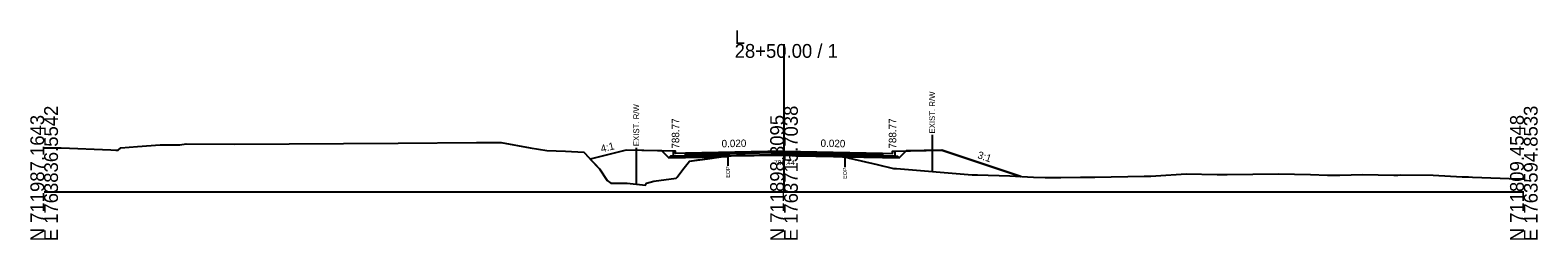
# Model space of a CAD drawing. Extents: x -26 to 5303, y -10 to 9578.
# Drawn here: x 997.2 to 1302.8, y 8490.3 to 8532.8 of the extents above; entities that cross this region are included whole.
import ezdxf

# ---------------------------------------------------------------- set-up
doc = ezdxf.new("R2010")
doc.units = 0
for name, color, linetype in [('Default', 7, 'Continuous'), ('Exist CMT Pavement', 7, 'Continuous'), ('Exist Cross Section Cell', 7, 'Continuous'), ('Exist XS Ground Line', 7, 'Continuous'), ('Old_Level_10', 7, 'Continuous'), ('Old_Level_3', 7, 'Continuous'), ('Prop CMT Conc Surface', 7, 'Continuous'), ('Prop CMT Concrete Structures', 7, 'Continuous'), ('Prop CMT Pvmt Course 1', 7, 'Continuous'), ('Prop CMT Pvmt Course 1 CG', 7, 'Continuous'), ('Prop CMT Pvmt Course 2', 7, 'Continuous'), ('Prop CMT Pvmt Course 3', 7, 'Continuous'), ('Prop CMT Pvmt Surface', 7, 'Continuous'), ('Prop CMT Slope Grass', 7, 'Continuous'), ('Prop CMT Subgrade Earthwork', 7, 'Continuous'), ('Prop XS Earthwork Shape', 7, 'Continuous'), ('Prop XS Hydro Elevations', 7, 'Continuous'), ('Prop XS SE Text', 7, 'Continuous'), ('Prop XS Side Slope Text', 7, 'Continuous'), ('Prop XS Wedging', 7, 'Continuous')]:
    doc.layers.add(name, color=color, linetype=linetype)

msp = doc.modelspace()

# ---------------------------------------------------------------- linework, layer by layer
at = {"layer": 'Exist CMT Pavement'}
msp.add_lwpolyline([(1138.63, 8507.34), (1140.35, 8507.37), (1140.82, 8507.37), (1142.14, 8507.38), (1143.12, 8507.39), (1143.93, 8507.41), (1145.04, 8507.42), (1146.22, 8507.43), (1147.51, 8507.42), (1149.4, 8507.43), (1150, 8507.44), (1150.75, 8507.45), (1151.57, 8507.39), (1152.42, 8507.35), (1152.87, 8507.34), (1153.48, 8507.33), (1154.66, 8507.31), (1155.53, 8507.3), (1156.45, 8507.28), (1157.7, 8507.24), (1158.24, 8507.22), (1158.63, 8507.22), (1160.02, 8507.19), (1161.86, 8507.13), (1162.35, 8507.1)], dxfattribs=at)
at = {"layer": 'Exist Cross Section Cell'}
for p, q in [((1150, 8500), (1150, 8529.97)), ((1000, 8500), (1150, 8500)), ((1150, 8500), (1300, 8500))]:
    msp.add_line(p, q, dxfattribs=at)
at = {"layer": 'Exist XS Ground Line'}
msp.add_lwpolyline([(1000, 8508.95), (1001.98, 8508.94), (1003.47, 8508.91), (1013.52, 8508.53), (1014.52, 8508.48), (1015.02, 8508.46), (1015.52, 8508.96), (1018.9, 8509.23), (1023.51, 8509.57), (1025.85, 8509.57), (1027.51, 8509.57), (1028.77, 8509.76), (1038.57, 8509.66), (1071.74, 8509.91), (1087.66, 8509.99), (1089.89, 8509.99), (1092.67, 8509.99), (1098.55, 8508.92), (1101.94, 8508.37), (1105.73, 8508.28), (1109.41, 8508.03), (1112.56, 8504.71), (1114.12, 8502.29), (1114.87, 8501.77), (1118.19, 8501.76), (1121.89, 8501.36), (1122.14, 8501.79), (1123.59, 8502.22), (1128.15, 8502.82), (1128.35, 8503.02), (1129.5, 8504.52), (1130.86, 8506.27), (1135.94, 8507.04), (1138.63, 8507.33), (1139.28, 8507.35), (1140.35, 8507.37), (1140.82, 8507.37), (1142.14, 8507.38), (1143.12, 8507.39), (1143.93, 8507.41), (1145.04, 8507.42), (1145.72, 8507.43), (1146.22, 8507.43), (1147.51, 8507.42), (1149.4, 8507.43), (1150, 8507.44), (1150.75, 8507.45), (1151.57, 8507.39), (1152.42, 8507.35), (1152.87, 8507.34), (1153.48, 8507.33), (1154.66, 8507.31), (1155.53, 8507.3), (1157.7, 8507.24), (1158.24, 8507.22), (1158.63, 8507.22), (1160.02, 8507.19), (1161.86, 8507.13), (1162.35, 8507.1), (1163.27, 8506.87), (1168.86, 8505.56), (1172.19, 8504.75), (1172.78, 8504.73), (1188.18, 8503.47), (1188.62, 8503.46), (1189.22, 8503.44), (1195.78, 8503.25), (1200.59, 8502.99), (1202.93, 8502.91), (1206.11, 8502.91), (1210.08, 8502.98), (1213.01, 8503.01), (1222.99, 8503.17), (1224.39, 8503.2), (1225.42, 8503.27), (1231.55, 8503.68), (1237.84, 8503.52), (1238.7, 8503.54), (1239.87, 8503.52), (1250.25, 8503.69), (1256.76, 8503.57), (1260.16, 8503.43), (1262.66, 8503.43), (1267.31, 8503.52), (1273.64, 8503.43), (1274.47, 8503.43), (1275.08, 8503.44), (1281.62, 8503.41), (1287.49, 8503.08), (1288.78, 8503.06), (1289.58, 8503.01), (1298.89, 8502.67), (1300, 8502.65)], dxfattribs=at)
at = {"layer": 'Old_Level_10'}
for p, q in [((1180.04, 8511.54), (1180.04, 8504.14)), ((1120.04, 8508.96), (1120.04, 8501.56)), ((1138.63, 8507.33), (1138.63, 8505.28)), ((1162.35, 8507.1), (1162.35, 8505.05))]:
    msp.add_line(p, q, dxfattribs=at)
at = {"layer": 'Prop CMT Conc Surface'}
for points in [[(1128, 8507.77), (1128, 8508.27), (1127.5, 8508.27)], [(1130, 8507.89), (1128, 8507.77)], [(1170, 8507.89), (1172, 8507.77)], [(1172, 8507.77), (1172, 8508.27), (1172.5, 8508.27)]]:
    msp.add_lwpolyline(points, dxfattribs=at)
at = {"layer": 'Prop CMT Concrete Structures'}
for points in [[(1130, 8507.89), (1128, 8507.77), (1128, 8508.27), (1127.5, 8508.27)], [(1127.5, 8508.27), (1127.5, 8507.26), (1130, 8507.31)], [(1130, 8507.31), (1130, 8507.89)], [(1170, 8507.89), (1172, 8507.77), (1172, 8508.27), (1172.5, 8508.27)], [(1172.5, 8508.27), (1172.5, 8507.26), (1170, 8507.31)], [(1170, 8507.31), (1170, 8507.89)]]:
    msp.add_lwpolyline(points, dxfattribs=at)
at = {"layer": 'Prop CMT Pvmt Course 1'}
for points in [[(1150, 8508.29), (1130, 8507.89)], [(1130, 8507.89), (1130, 8507.64)], [(1130, 8507.64), (1138.63, 8507.81)], [(1138.63, 8507.81), (1150, 8508.04)], [(1138.63, 8507.81), (1138.63, 8507.81)], [(1150, 8508.04), (1150, 8508.29)], [(1150, 8508.29), (1170, 8507.89)], [(1150, 8508.04), (1150, 8508.04), (1150, 8508.04)], [(1162.35, 8507.79), (1150, 8508.04)], [(1170, 8507.64), (1162.35, 8507.79)], [(1162.35, 8507.79), (1162.35, 8507.79)], [(1170, 8507.89), (1170, 8507.64)]]:
    msp.add_lwpolyline(points, dxfattribs=at)
at = {"layer": 'Prop CMT Pvmt Course 1 CG'}
for points in [[(1130, 8507.31), (1127, 8507.25), (1126.66, 8506.91)], [(1130, 8506.97), (1130, 8507.31)], [(1170, 8507.31), (1173, 8507.25), (1173.34, 8506.91)], [(1170, 8506.97), (1170, 8507.31)], [(1126.66, 8506.91), (1130, 8506.97)], [(1173.34, 8506.91), (1170, 8506.97)]]:
    msp.add_lwpolyline(points, dxfattribs=at)
at = {"layer": 'Prop CMT Pvmt Course 2'}
for points in [[(1138.63, 8507.81), (1130, 8507.64)], [(1130, 8507.64), (1130, 8507.31)], [(1130, 8507.31), (1138.63, 8507.48)], [(1138.63, 8507.48), (1138.63, 8507.81)], [(1162.35, 8507.46), (1162.35, 8507.79)], [(1162.35, 8507.79), (1170, 8507.64)], [(1170, 8507.31), (1162.35, 8507.46)], [(1170, 8507.64), (1170, 8507.31)]]:
    msp.add_lwpolyline(points, dxfattribs=at)
at = {"layer": 'Prop CMT Pvmt Course 3'}
for points in [[(1138.63, 8507.48), (1130, 8507.31)], [(1130, 8507.31), (1130, 8506.97)], [(1130, 8506.97), (1138.63, 8507.15)], [(1138.63, 8507.15), (1138.63, 8507.48)], [(1162.35, 8507.46), (1170, 8507.31)], [(1162.35, 8507.13), (1162.35, 8507.46)], [(1170, 8506.97), (1162.35, 8507.13)], [(1170, 8507.31), (1170, 8506.97)]]:
    msp.add_lwpolyline(points, dxfattribs=at)
at = {"layer": 'Prop CMT Pvmt Surface'}
for points in [[(1150, 8508.29), (1130, 8507.89)], [(1150, 8508.29), (1170, 8507.89)]]:
    msp.add_lwpolyline(points, dxfattribs=at)
at = {"layer": 'Prop CMT Slope Grass'}
for points in [[(1127.5, 8508.27), (1118, 8508.46), (1110.73, 8506.64)], [(1172.5, 8508.27), (1182, 8508.46), (1198, 8503.13)]]:
    msp.add_lwpolyline(points, dxfattribs=at)
at = {"layer": 'Prop CMT Subgrade Earthwork'}
for p, q in [((1138.63, 8507.34), (1138.63, 8507.15)), ((1162.35, 8507.13), (1162.35, 8507.1))]:
    msp.add_line(p, q, dxfattribs=at)
for points in [[(1130, 8506.97), (1126.66, 8506.91), (1125.25, 8508.32)], [(1138.63, 8507.15), (1130, 8506.97)], [(1162.35, 8507.13), (1170, 8506.97)], [(1170, 8506.97), (1173.34, 8506.91), (1174.75, 8508.32)]]:
    msp.add_lwpolyline(points, dxfattribs=at)
at = {"layer": 'Prop XS Earthwork Shape'}
for points in [[(1118.19, 8501.76), (1121.89, 8501.36), (1122.14, 8501.79), (1123.59, 8502.22), (1128.15, 8502.82), (1128.35, 8503.02), (1129.5, 8504.52), (1130.86, 8506.27), (1134.49, 8506.69), (1137.23, 8507.12), (1130, 8506.97), (1126.66, 8506.91), (1125.25, 8508.32), (1118, 8508.46), (1110.73, 8506.64), (1112.56, 8504.71), (1114.12, 8502.29), (1114.87, 8501.77)], [(1138.63, 8507.15), (1137.23, 8507.12), (1138.63, 8507.34)], [(1168.86, 8505.56), (1172.19, 8504.75), (1172.78, 8504.73), (1188.18, 8503.47), (1189.22, 8503.44), (1195.78, 8503.25), (1198, 8503.13), (1182, 8508.46), (1174.75, 8508.32), (1173.34, 8506.91), (1170, 8506.97), (1162.35, 8507.13), (1162.35, 8507.1), (1163.27, 8506.87)]]:
    msp.add_lwpolyline(points, close=True, dxfattribs=at)
at = {"layer": 'Prop XS Wedging'}
for points in [[(1138.63, 8507.33), (1138.63, 8507.81), (1139.04, 8507.82), (1140.35, 8507.85), (1140.82, 8507.86), (1142.14, 8507.88), (1143.12, 8507.9), (1143.93, 8507.92), (1145.04, 8507.94), (1146.22, 8507.97), (1147.51, 8507.99), (1149.4, 8508.03), (1150, 8508.04), (1150.75, 8508.03), (1151.57, 8508.01), (1152.42, 8507.99), (1152.87, 8507.98), (1153.48, 8507.97), (1154.66, 8507.95), (1155.53, 8507.93), (1156.45, 8507.91), (1157.7, 8507.89), (1158.24, 8507.88), (1158.63, 8507.87), (1160.02, 8507.84), (1161.86, 8507.8), (1162.35, 8507.79), (1162.35, 8507.1), (1161.86, 8507.13), (1160.02, 8507.19), (1158.63, 8507.22), (1158.24, 8507.22), (1157.7, 8507.24), (1156.45, 8507.28), (1155.53, 8507.3), (1154.66, 8507.31), (1153.48, 8507.33), (1152.87, 8507.34), (1152.42, 8507.35), (1151.57, 8507.39), (1150.75, 8507.45), (1150, 8507.44), (1149.4, 8507.43), (1147.51, 8507.42), (1146.22, 8507.43), (1145.04, 8507.42), (1143.93, 8507.41), (1143.12, 8507.4), (1142.14, 8507.38), (1140.82, 8507.37), (1140.35, 8507.37), (1139.04, 8507.34)], [(1147.83, 8507.42), (1148.08, 8507.67), (1149.4, 8507.7), (1150, 8507.71), (1150.59, 8507.7), (1150.83, 8507.45), (1150, 8507.44), (1149.4, 8507.43)], [(1150.61, 8507.45), (1150.86, 8507.69), (1151.57, 8507.68), (1152.42, 8507.66), (1152.87, 8507.65), (1153.48, 8507.64), (1154.66, 8507.62), (1155.53, 8507.6), (1156.45, 8507.58), (1157.7, 8507.56), (1158.24, 8507.55), (1158.63, 8507.54), (1160.02, 8507.51), (1161.86, 8507.47), (1162.35, 8507.46), (1162.35, 8507.1), (1161.86, 8507.13), (1160.02, 8507.19), (1158.63, 8507.22), (1158.24, 8507.22), (1157.7, 8507.24), (1156.45, 8507.28), (1155.53, 8507.3), (1154.66, 8507.31), (1153.48, 8507.33), (1152.87, 8507.34), (1152.42, 8507.35), (1151.57, 8507.39), (1150.75, 8507.45)]]:
    msp.add_lwpolyline(points, close=True, dxfattribs=at)

# ---------------------------------------------------------------- texts
at = {"layer": 'Default'}
msp.add_text('-', height=0.0001, dxfattribs=at).set_placement((1000, 8500))
at = {"layer": 'Exist Cross Section Cell'}
for s, p in [('L', (1140, 8529.97)), ('28+50.00 / 1', (1140, 8527.17))]:
    msp.add_text(s, height=2.8, dxfattribs=at).set_placement(p)
for s, p in [('E 1763836.5542', (1002.8, 8490)), ('E 1763715.7038', (1152.8, 8490)), ('E 1763594.8533', (1302.8, 8490)), ('N 711987.1643', (1000, 8490)), ('N 711898.3095', (1150, 8490)), ('N 711809.4548', (1300, 8490))]:
    msp.add_text(s, height=2.8, rotation=90, dxfattribs=at).set_placement(p)
at = {"layer": 'Old_Level_10'}
for s, height, p in [('EXIST. R/W', 1.181, (1180.63, 8511.84)), ('EXIST. R/W', 1.181, (1120.63, 8509.27)), ('EOP', 0.787, (1139.02, 8502.89)), ('EOP', 0.787, (1162.75, 8502.65))]:
    msp.add_text(s, height=height, rotation=90, dxfattribs=at).set_placement(p)
at = {"layer": 'Old_Level_3'}
msp.add_text('788.44', height=1, dxfattribs=at).set_placement((1147.95, 8505.44))
at = {"layer": 'Prop XS Hydro Elevations'}
for p in [(1128.75, 8508.77), (1172.75, 8508.77)]:
    msp.add_text('788.77', height=1.5, rotation=90, dxfattribs=at).set_placement(p)
at = {"layer": 'Prop XS SE Text'}
for rotation, p in [(1.1458, (1137.36, 8509.04)), (358.8542, (1157.4, 8509.14))]:
    msp.add_text('0.020', height=1.5, rotation=rotation, dxfattribs=at).set_placement(p)
at = {"layer": 'Prop XS Side Slope Text'}
for s, rotation, p in [('4:1', 14.0362, (1113.03, 8507.99)), ('3:1', 341.5651, (1189.11, 8506.88))]:
    msp.add_text(s, height=1.5, rotation=rotation, dxfattribs=at).set_placement(p)

doc.saveas('drawing.dxf')
